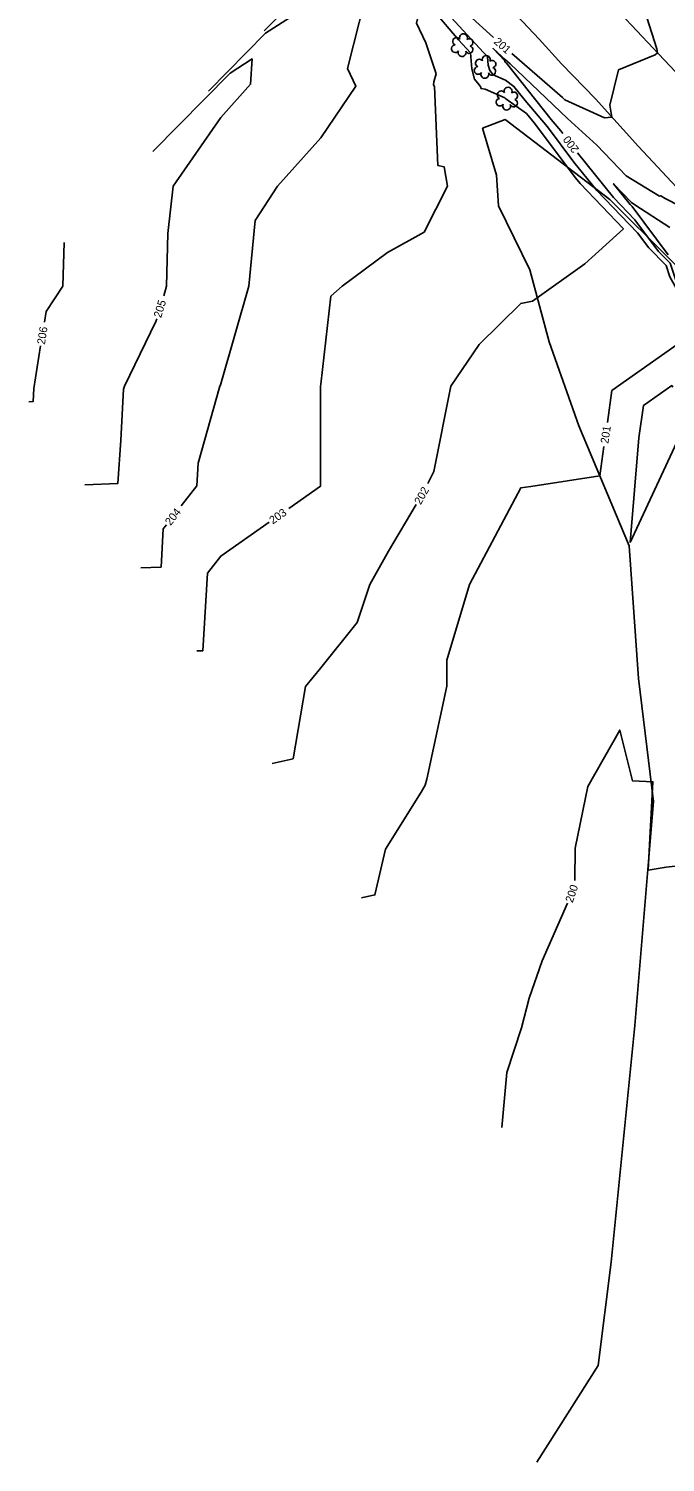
# Model space of a CAD drawing. Extents: x 2086416 to 2115205, y 575507 to 632762.
# Drawn here: x 2109949.5 to 2110108.6, y 581916.1 to 582274.4 of the extents above; entities that cross this region are included whole.
import ezdxf

# ---------------------------------------------------------------- set-up
doc = ezdxf.new("R2010")
doc.units = 0
for name, color, linetype in [('DTM Contours Major', 7, 'Continuous'), ('DTM Contours Major Text', 7, 'Continuous'), ('DTM Contours Minor', 7, 'Continuous'), ('DTM Contours Minor Text', 7, 'Continuous'), ('Exist Roads EOP', 7, 'Continuous'), ('Exist Vegetation Shrub CELL', 7, 'Continuous'), ('Exist Vegetation Woods Line', 7, 'Continuous')]:
    doc.layers.add(name, color=color, linetype=linetype)

# ---------------------------------------------------------------- blocks, each defined once
blk = doc.blocks.new('EXIST VEGETATION SHRUB')
at = {"layer": 'Exist Vegetation Shrub CELL'}
blk.add_line((0, 0), (0, 0), dxfattribs=at)
for centre, radius, start, end in [((-0.036, -0.0141), 0.0191, 95.10992, 327.95341), ((-0.0297, 0.0225), 0.0194, 35.89076, 245.42165), ((0.0046, 0.0408), 0.0198, 334.83907, 200.47174), ((0.0334, 0.0174), 0.0186, 284.45672, 126.08612), ((-0.0026, -0.0337), 0.0197, 151.27966, 21.38702), ((0.0327, -0.0186), 0.0187, 204.99133, 73.46012)]:
    blk.add_arc(centre, radius, start, end, dxfattribs=at)

msp = doc.modelspace()

# ---------------------------------------------------------------- linework, layer by layer
at = {"layer": 'DTM Contours Major'}
for points in [[(2110120.4, 582226.6), (2110120.27, 582225.14), (2110115.94, 582228.14), (2110108.58, 582231.97), (2110107.48, 582232.63), (2110107.15, 582232.52), (2110098.82, 582237.61), (2110091.52, 582245.28), (2110084.17, 582251.94), (2110069.86, 582265.54), (2110068.65, 582266.59), (2110065.58, 582269.39), (2110068.47, 582266.29), (2110068.49, 582266.13), (2110068.51, 582266.04), (2110068.58, 582265.96), (2110068.8, 582265.85), (2110068.96, 582265.74), (2110080.07, 582251.64), (2110082.51, 582248.8), (2110083.01, 582248.14)], [(2109980.52, 582243.69), (2109999.86, 582263.28), (2110005.33, 582266.8), (2110004.98, 582260.49), (2109997.53, 582252.16), (2109985.6, 582235.01), (2109984.29, 582223.22), (2109983.99, 582210.01), (2109983.26, 582207.61)], [(2110086.65, 582243.38), (2110095.68, 582232.16), (2110101, 582226.63), (2110106.9, 582218.72), (2110109.82, 582215.75), (2110111.89, 582209.48), (2110116.13, 582201.87), (2110118.59, 582200.15), (2110121.31, 582196.4), (2110137.22, 582178.92), (2110139.86, 582175.47), (2110149.85, 582167.21)], [(2109981.52, 582201.87), (2109981.31, 582201.2), (2109973.45, 582185.01), (2109973.24, 582184.27), (2109972.5, 582171.5), (2109971.78, 582160.71), (2109963.51, 582160.39)], [(2110099.85, 582145.93), (2110102.02, 582172.15), (2110103.18, 582180.21), (2110110.21, 582185.17), (2110110.46, 582184.79)], [(2110113.79, 582179.8), (2110114.86, 582178.19), (2110099.85, 582145.93)], [(2110123.82, 582066.52), (2110108.81, 582064.84), (2110104.3, 582064.09), (2110105.52, 582086.17), (2110100.43, 582086.39), (2110097.21, 582099.07), (2110089.24, 582085.01), (2110086.09, 582069.62), (2110086.03, 582061.46)], [(2110084.13, 582055.85), (2110077.85, 582041.39), (2110074.58, 582032.08), (2110072.69, 582024.7), (2110068.99, 582013.49), (2110067.79, 581999.76)]]:
    msp.add_lwpolyline(points, dxfattribs=at)
at = {"layer": 'DTM Contours Minor'}
for points in [[(2110008.36, 582273.85), (2110017.6, 582283.2), (2110035.78, 582294.88), (2110045.01, 582284.9), (2110047.45, 582279.81), (2110046.42, 582275.74), (2110048.77, 582270.85), (2110051.34, 582263.12), (2110050.77, 582261.05), (2110050.67, 582260.36), (2110050.96, 582259.93), (2110051.79, 582240.17), (2110053.34, 582239.88), (2110054.19, 582234.99), (2110048.32, 582223.48), (2110039.2, 582218.43), (2110027.88, 582210.01), (2110025, 582207.52), (2110022.5, 582185.57), (2110022.45, 582185.01), (2110022.43, 582184.94), (2110022.43, 582160.01), (2110014.52, 582154.48)], [(2109994.44, 582258.77), (2110008.73, 582273.24), (2110035.26, 582290.28), (2110035.13, 582287.82), (2110029.17, 582264.4), (2110031.29, 582260), (2110022.5, 582247.11), (2110011.69, 582235.01), (2110006.08, 582226.42), (2110004.5, 582210.01), (2109997.5, 582185.58), (2109997.37, 582185.15), (2109997.31, 582185.02), (2109991.84, 582165.81), (2109991.51, 582160.14), (2109987.61, 582155.09)], [(2110050.82, 582278.78), (2110056.91, 582271.61), (2110059.95, 582268.35), (2110060.26, 582264.36), (2110060.92, 582261.78), (2110062.13, 582260.3), (2110062.5, 582259.74), (2110062.52, 582259.45), (2110063.63, 582259.24), (2110068.48, 582257.06), (2110068.77, 582256.86), (2110073.89, 582253.15), (2110075.85, 582250.87), (2110086.14, 582237.08), (2110087.3, 582235.65), (2110098.15, 582224.38), (2110088.48, 582215.57), (2110075.43, 582206.3), (2110072.5, 582205.71), (2110062.12, 582195.46), (2110055.02, 582185.03), (2110050.74, 582163.73), (2110049.27, 582160.68)], [(2110055.08, 582277.12), (2110064.21, 582267.32), (2110064.38, 582265.25), (2110064.72, 582263.91), (2110065.6, 582262.82), (2110068.64, 582261.46), (2110070.76, 582259.93), (2110073.56, 582256.38), (2110079.18, 582249.83), (2110085.75, 582241.03), (2110091.49, 582233.9), (2110101.65, 582223.35), (2110104.47, 582219.58), (2110108.83, 582215.15), (2110109.74, 582212.36), (2110116.87, 582199.58), (2110115.81, 582198.41), (2110095.28, 582183.92), (2110094.13, 582175.93)], [(2110065.71, 582272.12), (2110059.45, 582277.85)], [(2110104.03, 582277.19), (2110106.53, 582269.37), (2110106.7, 582268.34), (2110106.11, 582267.85), (2110096.94, 582264.09), (2110094.75, 582255.22), (2110095.28, 582252.26), (2110093.4, 582252.06), (2110083.51, 582256.62), (2110083.01, 582257.07), (2110082.89, 582257.19), (2110070.23, 582268.17)], [(2110109.78, 582224.7), (2110101.02, 582230.38), (2110100.15, 582230.92), (2110095.68, 582235.61), (2110099.86, 582230.42), (2110100.35, 582229.91), (2110109.33, 582217.86)], [(2109958.38, 582220.9), (2109958.01, 582210.01), (2109953.85, 582203.66), (2109953.44, 582201.02)], [(2109952.5, 582195.09), (2109950.83, 582184.45), (2109950.62, 582181.19), (2109949.51, 582181.14)], [(2110093.28, 582169.99), (2110092.22, 582162.65), (2110075.04, 582159.94), (2110072.5, 582159.61), (2110059.69, 582135.46), (2110054.02, 582116.6), (2110053.99, 582110.1), (2110049.01, 582086.79), (2110048.61, 582085.35), (2110047.57, 582083.56), (2110038.65, 582069.29), (2110036.05, 582057.91), (2110032.72, 582057.18)], [(2110046.36, 582155.43), (2110039.47, 582143.79), (2110034.75, 582135.43), (2110031.58, 582125.99), (2110022.5, 582114.63), (2110018.66, 582110.01), (2110015.59, 582091.92), (2110010.33, 582090.76)], [(2109983.94, 582150.34), (2109983.16, 582149.34), (2109982.59, 582139.83), (2109977.51, 582139.63)], [(2110009.61, 582151.04), (2109997.5, 582142.56), (2109994.21, 582138.3), (2109993.04, 582118.93), (2109991.52, 582118.87)]]:
    msp.add_lwpolyline(points, dxfattribs=at)
at = {"layer": 'Exist Roads EOP'}
for points in [[(2110283.42, 582080.08), (2110269.79, 582094.77), (2110258.57, 582106.89), (2110244.84, 582121.04), (2110232.61, 582133.97), (2110220.43, 582147.01), (2110205.56, 582162.74), (2110193.7, 582175.26), (2110182.38, 582187.32), (2110170.57, 582200.14), (2110157.55, 582213.9), (2110148.13, 582223.91), (2110139.67, 582233.18), (2110129.17, 582244.2), (2110118.25, 582256.11), (2110105.57, 582269.53), (2110093.37, 582282.59), (2110082.14, 582294.76), (2110071.88, 582305.53), (2110059.32, 582319.17)], [(2110044.03, 582306.54), (2110057.72, 582292.25), (2110067.42, 582282.08), (2110077.05, 582271.73), (2110082.67, 582265.54), (2110091.18, 582256.81), (2110101.9, 582244.92), (2110112.61, 582233.51), (2110124.83, 582220.15), (2110138.66, 582205.71), (2110150.44, 582192.87), (2110163.31, 582179.2), (2110176.51, 582165.18), (2110187.09, 582154.1), (2110200.16, 582140.29), (2110212.15, 582128.06), (2110221.2, 582117.92), (2110235.62, 582102.6), (2110247.94, 582089.65), (2110262.41, 582074.68), (2110272.71, 582063.48), (2110283.25, 582052.48)]]:
    msp.add_lwpolyline(points, dxfattribs=at)
at = {"layer": 'Exist Vegetation Woods Line'}
for points in [[(2110076.47, 581916.11), (2110091.85, 581940.31), (2110095.05, 581966.16), (2110101.03, 582025.24), (2110105.7, 582081.27), (2110101.91, 582111.98), (2110099.6, 582145.14), (2110087.04, 582175.13), (2110079.58, 582196.1), (2110074.74, 582214.13), (2110066.9, 582230.06), (2110066.42, 582237.72), (2110062.96, 582249.48), (2110068.55, 582251.65)], [(2110068.55, 582251.65), (2110094.73, 582231.68), (2110124.29, 582202.28), (2110166.88, 582155.97), (2110198.23, 582122.47), (2110225.6, 582089.15), (2110269.57, 582041.09)]]:
    msp.add_lwpolyline(points, dxfattribs=at)

# ---------------------------------------------------------------- block references
at = {"layer": 'Exist Vegetation Shrub CELL', "xscale": 50, "yscale": 50}
for p in [(2110057.95, 582270.06), (2110063.63, 582264.63), (2110069.09, 582256.71)]:
    msp.add_blockref('EXIST VEGETATION SHRUB', p, dxfattribs=at)

# ---------------------------------------------------------------- texts
at = {"layer": 'DTM Contours Major Text'}
for s, rotation, p in [('200', 127.4642, (2110087.18, 582244.27)), ('205', 73.0822, (2109982.59, 582201.96)), ('200', 71.315, (2110085.44, 582055.81))]:
    msp.add_text(s, height=2, rotation=rotation, dxfattribs=at).set_placement(p)
at = {"layer": 'DTM Contours Minor Text'}
for s, rotation, p in [('201', 318.7867, (2110065.59, 582270.87)), ('206', 81.0751, (2109953.55, 582195.33)), ('201', 81.8171, (2110094.37, 582170.57)), ('202', 60.9732, (2110047.48, 582155.26)), ('204', 52.2869, (2109984.97, 582150.04)), ('203', 34.9948, (2110010.51, 582150.44))]:
    msp.add_text(s, height=2, rotation=rotation, dxfattribs=at).set_placement(p)

doc.saveas('drawing.dxf')
